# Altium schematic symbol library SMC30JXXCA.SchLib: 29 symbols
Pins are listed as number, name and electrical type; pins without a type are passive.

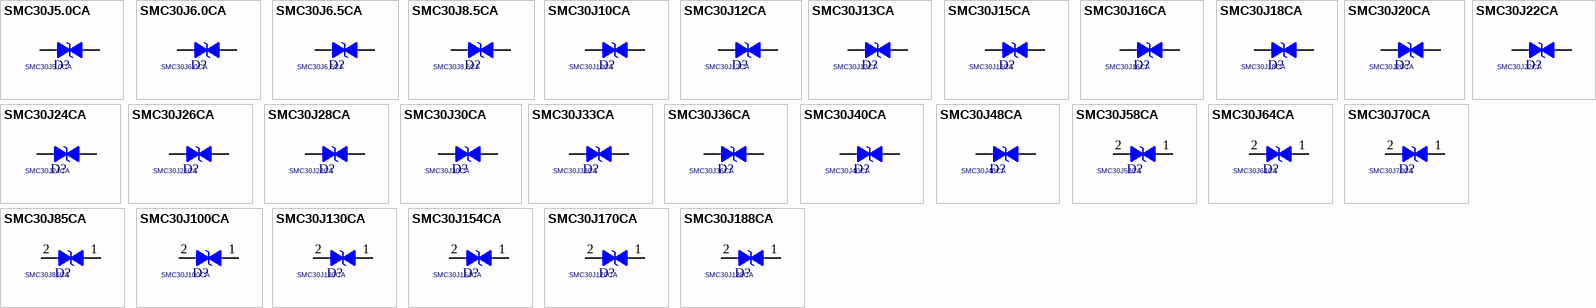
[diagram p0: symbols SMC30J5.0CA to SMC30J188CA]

## SMC30J5.0CA
designator D?
footprint ST_SMCB
pins: 1, 2

## SMC30J6.0CA
designator D?
footprint ST_SMCB
pins: 1, 2

## SMC30J6.5CA
designator D?
footprint ST_SMCB
pins: 1, 2

## SMC30J8.5CA
designator D?
footprint ST_SMCB
pins: 1, 2

## SMC30J10CA
designator D?
footprint ST_SMCB
pins: 1, 2

## SMC30J12CA
designator D?
footprint ST_SMCB
pins: 1, 2

## SMC30J13CA
designator D?
footprint ST_SMCB
pins: 1, 2

## SMC30J15CA
designator D?
footprint ST_SMCB
pins: 1, 2

## SMC30J16CA
designator D?
footprint ST_SMCB
pins: 1, 2

## SMC30J18CA
designator D?
footprint ST_SMCB
pins: 1, 2

## SMC30J20CA
designator D?
footprint ST_SMCB
pins: 1, 2

## SMC30J22CA
designator D?
footprint ST_SMCB
pins: 1, 2

## SMC30J24CA
designator D?
footprint ST_SMCB
pins: 1, 2

## SMC30J26CA
designator D?
footprint ST_SMCB
pins: 1, 2

## SMC30J28CA
designator D?
footprint ST_SMCB
pins: 1, 2

## SMC30J30CA
designator D?
footprint ST_SMCB
pins: 1, 2

## SMC30J33CA
designator D?
footprint ST_SMCB
pins: 1, 2

## SMC30J36CA
designator D?
footprint ST_SMCB
pins: 1, 2

## SMC30J40CA
designator D?
footprint ST_SMCB
pins: 1, 2

## SMC30J48CA
designator D?
footprint ST_SMCB
pins: 1, 2

## SMC30J58CA
designator D?
footprint ST_SMCB
pins: 1, 2

## SMC30J64CA
designator D?
footprint ST_SMCB
pins: 1, 2

## SMC30J70CA
designator D?
footprint ST_SMCB
pins: 1, 2

## SMC30J85CA
designator D?
footprint ST_SMCB
pins: 1, 2

## SMC30J100CA
designator D?
footprint ST_SMCB
pins: 1, 2

## SMC30J130CA
designator D?
footprint ST_SMCB
pins: 1, 2

## SMC30J154CA
designator D?
footprint ST_SMCB
pins: 1, 2

## SMC30J170CA
designator D?
footprint ST_SMCB
pins: 1, 2

## SMC30J188CA
designator D?
footprint ST_SMCB
pins: 1, 2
